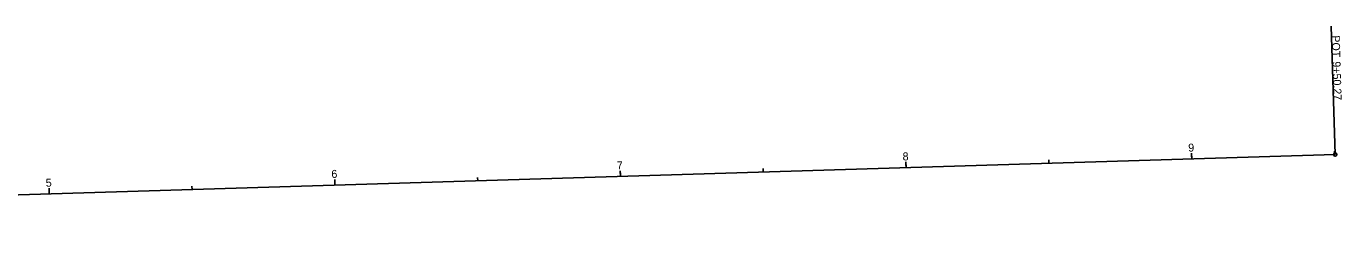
# Model space of a CAD drawing. Extents: x 2189302 to 2190256, y 657273 to 657356.
# Drawn here: x 2189795.5 to 2190255.9, y 657273.6 to 657347.8 of the extents above; entities that cross this region are included whole.
import ezdxf

# ---------------------------------------------------------------- set-up
doc = ezdxf.new("R2010")
doc.units = 0
for name, color, linetype in [('_CIVIL_CONSTRUCTION', 7, 'Continuous'), ('BR_P_Rail_Object', 7, 'Continuous'), ('BR_X_SV_Deck_Floor', 7, 'Continuous'), ('UT_X_Electric', 7, 'Continuous')]:
    doc.layers.add(name, color=color, linetype=linetype)

msp = doc.modelspace()

# ---------------------------------------------------------------- linework, layer by layer
at = {"layer": '_CIVIL_CONSTRUCTION'}
msp.add_line((2189303.83, 657273.65), (2190253.65, 657302.85), dxfattribs=at)
at = {"layer": 'BR_P_Rail_Object'}
for p, q in [((2190253.65, 657302.85), (2190252.26, 657347.83)), ((2190153.42, 657299.77), (2190153.39, 657300.97)), ((2190203.4, 657301.3), (2190203.34, 657303.3)), ((2190253.38, 657302.84), (2190253.34, 657304.04)), ((2190003.49, 657295.16), (2190003.43, 657297.16)), ((2190053.47, 657296.69), (2190053.43, 657297.89)), ((2190103.45, 657298.23), (2190103.39, 657300.23)), ((2189853.57, 657290.55), (2189853.53, 657291.75)), ((2189903.54, 657292.08), (2189903.48, 657294.08)), ((2189953.52, 657293.62), (2189953.48, 657294.82)), ((2189803.59, 657289.01), (2189803.53, 657291.01))]:
    msp.add_line(p, q, dxfattribs=at)
msp.add_circle((2190253.65, 657302.85), 0.6, dxfattribs=at)
at = {"layer": 'BR_X_SV_Deck_Floor'}
for p, q in [((2190253.65, 657302.85), (2190252.26, 657347.83)), ((2189803.59, 657289.01), (2189803.55, 657290.21))]:
    msp.add_line(p, q, dxfattribs=at)
msp.add_circle((2190253.65, 657302.85), 0.6, dxfattribs=at)
at = {"layer": 'UT_X_Electric'}
for p, q in [((2190253.65, 657302.85), (2190252.26, 657347.83)), ((2190203.4, 657301.3), (2190203.36, 657302.5)), ((2190003.49, 657295.16), (2190003.46, 657296.36)), ((2190103.45, 657298.23), (2190103.41, 657299.43)), ((2189903.54, 657292.08), (2189903.51, 657293.28)), ((2189803.59, 657289.01), (2189803.53, 657291.01))]:
    msp.add_line(p, q, dxfattribs=at)
msp.add_circle((2190253.65, 657302.85), 0.6, dxfattribs=at)

# ---------------------------------------------------------------- texts
at = {"layer": 'BR_P_Rail_Object'}
for s, rotation, p in [('POT', 271.761, (2190252.41, 657344.59)), ('9+50.27', 271.761, (2190252.69, 657335.47)), ('9', 1.761, (2190202.24, 657303.82)), ('7', 1.761, (2190002.25, 657297.62)), ('8', 1.761, (2190102.27, 657300.74)), ('6', 1.761, (2189902.35, 657294.6)), ('5', 1.761, (2189802.39, 657291.52))]:
    msp.add_text(s, height=2.8, rotation=rotation, dxfattribs=at).set_placement(p)
at = {"layer": 'BR_X_SV_Deck_Floor'}
for s, p in [('POT', (2190252.41, 657344.59)), ('9+50.27', (2190252.69, 657335.47))]:
    msp.add_text(s, height=2.8, rotation=271.761, dxfattribs=at).set_placement(p)
at = {"layer": 'UT_X_Electric'}
for s, rotation, p in [('POT', 271.761, (2190252.41, 657344.59)), ('9+50.27', 271.761, (2190252.69, 657335.47)), ('5', 1.761, (2189802.39, 657291.52))]:
    msp.add_text(s, height=2.8, rotation=rotation, dxfattribs=at).set_placement(p)

doc.saveas('drawing.dxf')
